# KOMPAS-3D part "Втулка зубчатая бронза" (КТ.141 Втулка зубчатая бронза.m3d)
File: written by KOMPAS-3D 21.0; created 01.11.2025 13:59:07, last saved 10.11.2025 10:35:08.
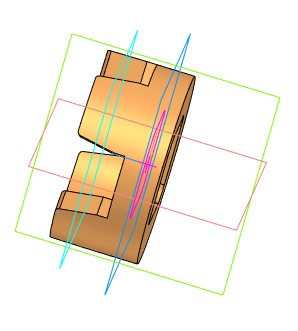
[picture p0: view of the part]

Document properties: Полное имя файла: C:\Users\User\Desktop\Pelorus PRO доработки\ЗАФИКСИРОВАЛИ\Втулка зубчатая бронза\КТ.141 Втулка зубчатая бронза.m3d; Автор: User

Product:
- Part/product: Втулка зубчатая бронза
    Материал: БрАЖ9-4  ГОСТ 18175-78 (density 7500 kg/m3)
    Масса: 0.10931
    Форматы листов документа: A4

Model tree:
1. Эскиз:1
2. Элемент выдавливания:1
     Расстояние 2 = 4.5
3. Смещенная плоскость:1  (with: Элемент выдавливания:1)
4. Эскиз:2  (with: Элемент выдавливания:1)
5. Элемент выдавливания:2
     Расстояние 1 = 10; Угол 1 = 10; Расстояние 2 = 4.75; Угол 2 = 10
6. Эскиз:3  (with: Элемент выдавливания:1)
7. Элемент выдавливания:3  (with: Элемент выдавливания:2)
     Расстояние 2 = 9.5
8. Элемент выдавливания:4  (with: Элемент выдавливания:2)
     Расстояние 2 = 1
9. Эскиз:4
10. Скругление:1  (with: Элемент выдавливания:2)
     Радиус = 1
11. Эскиз:5  (with: Элемент выдавливания:1)
12. Элемент выдавливания:7  (with: Элемент выдавливания:2)
     Расстояние 2 = 2.5
13. Элемент выдавливания:10  (labels: БрАЖ9-4  ГОСТ 18175-78)
     Расстояние 2 = 10; Угол 2 = 5

Expressions: (v12-7)/2; 45/2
